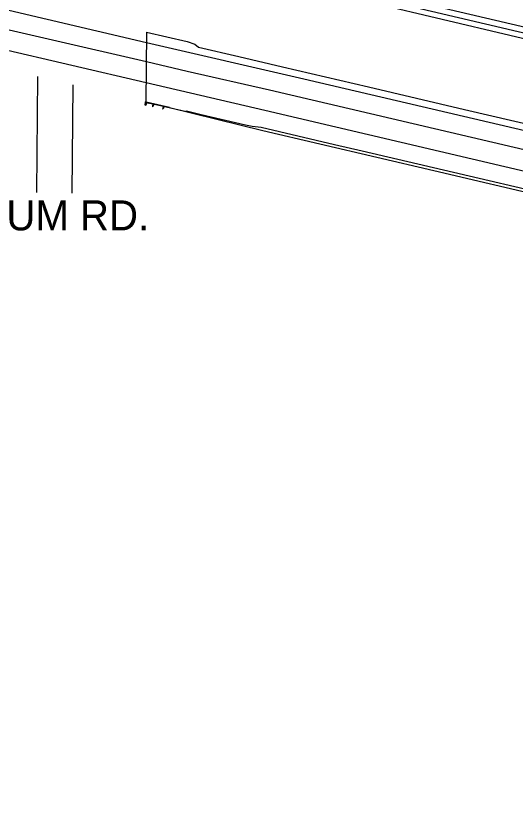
# Model space of a CAD drawing. Extents: x 1855721 to 1876784, y 662259 to 674089.
# Drawn here: x 1866935 to 1867234.5, y 670246.6 to 670728.1 of the extents above; entities that cross this region are included whole.
import ezdxf

# ---------------------------------------------------------------- set-up
doc = ezdxf.new("R2010")
doc.units = 0
for name, color, linetype in [('_CIVIL_CONSTRUCTION', 7, 'Continuous'), ('GE_X_Alignment_100_Bearings', 7, 'Continuous'), ('GE_X_Alignment_100_Curve_Data', 7, 'Continuous'), ('PV_X_EOP', 7, 'Continuous'), ('RD_P_GR_Rt', 7, 'Continuous'), ('SC_Scratch1', 7, 'Continuous'), ('ST_Details', 7, 'Continuous'), ('ST_Text', 7, 'Continuous')]:
    doc.layers.add(name, color=color, linetype=linetype)

msp = doc.modelspace()

# ---------------------------------------------------------------- linework, layer by layer
at = {"layer": '_CIVIL_CONSTRUCTION'}
msp.add_line((1867013.16, 670718.5), (1867012.76, 670676.58), dxfattribs=at)
msp.add_lwpolyline([(1867012.87, 670688.3), (1867083.99, 670671.71), (1867437.1, 670588.95), (1867669.88, 670534.52), (1867845.14, 670493.53), (1867928.1, 670474.12), (1868136.01, 670425.34)], dxfattribs=at)
at = {"layer": 'GE_X_Alignment_100_Bearings'}
msp.add_lwpolyline([(1866897.79, 670727.56), (1867013.17, 670700.87), (1867037.56, 670695.16), (1867086.73, 670683.9), (1867440.47, 670601.13), (1867916.5, 670489.44), (1868183.18, 670427.04), (1868411.44, 670373.26), (1868504.91, 670351.9), (1868605.05, 670329.69), (1868693.65, 670312.21), (1868779.08, 670297.26), (1868870.16, 670283.95), (1868961.03, 670272.66), (1869050.13, 670263.7), (1869134.71, 670256.54), (1869222.33, 670251.7), (1869304.01, 670248.74), (1869402.4, 670246.63)], dxfattribs=at)
at = {"layer": 'GE_X_Alignment_100_Curve_Data'}
for p, q in [((1866897.79, 670739.26), (1867013.1, 670712.33)), ((1866897.69, 670715.1), (1867012.95, 670688.28))]:
    msp.add_line(p, q, dxfattribs=at)
for points in [[(1869211.64, 670324.7), (1869181.41, 670325.88), (1869077.51, 670333.11), (1869033.93, 670337.15), (1868967.25, 670343.85), (1868933.99, 670347.93), (1868871.59, 670355.8), (1868843.23, 670360.06), (1868778.87, 670370.61), (1868737.1, 670377.6), (1868640.12, 670396.37), (1868613, 670401.82), (1868516.09, 670423.09), (1868416.31, 670446.1), (1868369.24, 670457), (1868181.82, 670500.43), (1868125.22, 670513.56), (1867987.22, 670546.13), (1867875.52, 670572.37), (1867459.74, 670669.94), (1867105.25, 670753), (1867057.66, 670764.25), (1867013.85, 670774.61)], [(1867013.1, 670712.33), (1867107.39, 670690.63), (1867437.01, 670613.48), (1867511.99, 670595.88), (1867874.8, 670510.7), (1867950.06, 670493.07), (1868168.73, 670441.99)]]:
    msp.add_lwpolyline(points, dxfattribs=at)
at = {"layer": 'PV_X_EOP'}
for p, q in [((1866947.78, 670691.88), (1866947.22, 670622.51)), ((1866969.01, 670686.85), (1866968.49, 670622.05))]:
    msp.add_line(p, q, dxfattribs=at)
at = {"layer": 'RD_P_GR_Rt'}
for points in [[(1867034.44, 670763.29), (1867109.18, 670745.61), (1867271.29, 670707.11), (1867411.77, 670673.57)], [(1867026.89, 670673.38), (1867082.92, 670659.65), (1867185.32, 670635.62), (1867324.6, 670602.93), (1867471.47, 670568.33), (1867621.14, 670533.37), (1867799.25, 670491.42), (1867900.04, 670468.06)]]:
    msp.add_lwpolyline(points, dxfattribs=at)
at = {"layer": 'SC_Scratch1'}
for points in [[(1867013.89, 670768.45), (1867037.96, 670762.82), (1867045.83, 670762.4), (1867047.65, 670762.28), (1867086.65, 670753.54), (1867086.77, 670753.98), (1867365.21, 670688.46), (1867472.77, 670663.16), (1867790.05, 670588.69), (1867994.77, 670540.69), (1868234.96, 670484.68)], [(1867013.16, 670718.5), (1867037.51, 670712.94), (1867042, 670711.21), (1867044.2, 670709.59), (1867068.36, 670703.88), (1867094.66, 670697.68), (1867146.22, 670685.66), (1867203.66, 670672.26), (1867275.17, 670655.59), (1867370.07, 670633.46), (1867484.93, 670606.62), (1867622.01, 670574.46), (1867714.16, 670552.85), (1867800.86, 670532.51), (1867916.15, 670505.47), (1867988.09, 670488.56), (1868059.57, 670471.76), (1868156.47, 670448.98)], [(1867012.76, 670676.58), (1867037.02, 670670.91), (1867037, 670671.33), (1867045.87, 670669.27), (1867072.52, 670663.05), (1867076.49, 670662.12), (1867081.85, 670661.49), (1867125.8, 670651.23), (1867142.34, 670647.38), (1867309.92, 670608.36), (1867388.87, 670589.99), (1867589.78, 670542.95), (1867666.82, 670524.88), (1867762.75, 670502.38), (1867895.63, 670471.22), (1867930.89, 670462.97), (1868063.82, 670432.01), (1868131.69, 670416.2), (1868263.49, 670385.32)]]:
    msp.add_lwpolyline(points, dxfattribs=at)
at = {"layer": 'ST_Details'}
for p, q in [((1867012.4, 670676.37), (1867012.1, 670675.02)), ((1867016.07, 670675.54), (1867012.17, 670676.42)), ((1867012.47, 670676.35), (1867012.17, 670675)), ((1867012.29, 670676.49), (1867012.27, 670676.4)), ((1867026.82, 670673.11), (1867012.27, 670676.4)), ((1867012.61, 670676.41), (1867012.29, 670676.49)), ((1867012.38, 670676.54), (1867012.37, 670676.47)), ((1867012.57, 670676.5), (1867012.38, 670676.54)), ((1867012.43, 670676.59), (1867012.41, 670676.53)), ((1867012.72, 670676.3), (1867012.42, 670674.95)), ((1867012.53, 670676.59), (1867012.45, 670676.61)), ((1867012.46, 670676.58), (1867012.45, 670676.53)), ((1867012.51, 670676.57), (1867012.5, 670676.51)), ((1867012.55, 670676.56), (1867012.53, 670676.51)), ((1867012.57, 670676.5), (1867012.55, 670676.43)), ((1867012.86, 670676.5), (1867012.61, 670676.41)), ((1867013.54, 670676.4), (1867013.48, 670676.13)), ((1867013.78, 670676.06), (1867013.84, 670676.33)), ((1867011.99, 670674.96), (1867012.01, 670675.04)), ((1867012.88, 670674.75), (1867011.99, 670674.96)), ((1867012.9, 670674.84), (1867012.01, 670675.04)), ((1867012.8, 670676.28), (1867012.49, 670674.93)), ((1867013.05, 670676.22), (1867012.75, 670674.87)), ((1867013.12, 670676.21), (1867012.82, 670674.86)), ((1867012.88, 670674.75), (1867012.9, 670674.84)), ((1867013.12, 670676.21), (1867013.06, 670676.22)), ((1867013.69, 670676.24), (1867013.68, 670676.21)), ((1867013.7, 670676.19), (1867013.92, 670676.14)), ((1867013.93, 670676.21), (1867013.71, 670676.26)), ((1867013.94, 670676.15), (1867013.95, 670676.18)), ((1867014.37, 670676.08), (1867014.37, 670676.06)), ((1867014.6, 670675.98), (1867014.38, 670676.03)), ((1867014.62, 670676.05), (1867014.4, 670676.1)), ((1867014.47, 670675.9), (1867014.53, 670676.18)), ((1867014.63, 670676), (1867014.64, 670676.02)), ((1867014.78, 670676.12), (1867014.71, 670675.85)), ((1867016.69, 670673.88), (1867016.69, 670673.9)), ((1867016.84, 670673.87), (1867016.69, 670673.9)), ((1867017.01, 670673.81), (1867016.69, 670673.88)), ((1867016.95, 670675.33), (1867016.73, 670674.36)), ((1867016.77, 670674.34), (1867016.73, 670674.35)), ((1867016.78, 670674.37), (1867016.77, 670674.34)), ((1867017.13, 670674.29), (1867016.78, 670674.37)), ((1867017.11, 670674.29), (1867016.79, 670674.36)), ((1867016.79, 670674.35), (1867016.79, 670674.36)), ((1867016.94, 670674.31), (1867016.79, 670674.35)), ((1867016.84, 670673.87), (1867016.94, 670674.31)), ((1867016.86, 670673.86), (1867016.96, 670674.31)), ((1867017.01, 670673.83), (1867016.86, 670673.86)), ((1867017.26, 670675.66), (1867016.93, 670674.21)), ((1867017.39, 670675.24), (1867016.96, 670675.34)), ((1867017.11, 670674.27), (1867016.96, 670674.31)), ((1867016.97, 670674.3), (1867016.97, 670674.29)), ((1867017.12, 670674.26), (1867016.97, 670674.29)), ((1867016.99, 670674.19), (1867017.02, 670674.31)), ((1867017, 670674.28), (1867016.99, 670674.23)), ((1867017.07, 670674.2), (1867016.99, 670674.22)), ((1867017.05, 670674.18), (1867016.99, 670674.19)), ((1867017.01, 670673.81), (1867017.01, 670673.83)), ((1867017.24, 670675.28), (1867017.02, 670674.31)), ((1867017.05, 670674.18), (1867017.08, 670674.3)), ((1867017.3, 670675.26), (1867017.08, 670674.3)), ((1867017.09, 670674.26), (1867017.08, 670674.21)), ((1867017.11, 670674.27), (1867017.11, 670674.29)), ((1867017.13, 670674.29), (1867017.12, 670674.26)), ((1867017.12, 670674.27), (1867017.12, 670674.25)), ((1867017.16, 670674.26), (1867017.12, 670674.26)), ((1867017.39, 670675.23), (1867017.17, 670674.26)), ((1867022.78, 670672.5), (1867022.78, 670672.52)), ((1867022.94, 670672.49), (1867022.78, 670672.52)), ((1867023.1, 670672.43), (1867022.78, 670672.5)), ((1867023.04, 670673.95), (1867022.82, 670672.98)), ((1867022.87, 670672.96), (1867022.83, 670672.97)), ((1867022.87, 670672.99), (1867022.87, 670672.96)), ((1867023.23, 670672.91), (1867022.87, 670672.99)), ((1867023.21, 670672.91), (1867022.89, 670672.98)), ((1867022.89, 670672.97), (1867022.89, 670672.98)), ((1867023.04, 670672.93), (1867022.89, 670672.97)), ((1867022.94, 670672.49), (1867023.04, 670672.93)), ((1867022.95, 670672.48), (1867023.05, 670672.93)), ((1867023.11, 670672.45), (1867022.95, 670672.48)), ((1867023.35, 670674.28), (1867023.02, 670672.83)), ((1867023.48, 670673.86), (1867023.05, 670673.96)), ((1867023.21, 670672.89), (1867023.05, 670672.93)), ((1867023.07, 670672.92), (1867023.06, 670672.91)), ((1867023.22, 670672.88), (1867023.06, 670672.91)), ((1867023.09, 670672.9), (1867023.08, 670672.86)), ((1867023.09, 670672.81), (1867023.12, 670672.93)), ((1867023.16, 670672.82), (1867023.09, 670672.84)), ((1867023.15, 670672.8), (1867023.09, 670672.81)), ((1867023.1, 670672.43), (1867023.11, 670672.45)), ((1867023.33, 670673.9), (1867023.12, 670672.93)), ((1867023.15, 670672.8), (1867023.18, 670672.92)), ((1867023.39, 670673.88), (1867023.18, 670672.92)), ((1867023.19, 670672.88), (1867023.18, 670672.83)), ((1867023.21, 670672.89), (1867023.21, 670672.91)), ((1867023.23, 670672.91), (1867023.22, 670672.88)), ((1867023.22, 670672.89), (1867023.22, 670672.88)), ((1867023.26, 670672.88), (1867023.22, 670672.88)), ((1867023.49, 670673.85), (1867023.27, 670672.88)), ((1867025.81, 670673.34), (1867025.87, 670673.61)), ((1867025.97, 670673.3), (1867026.03, 670673.58)), ((1867026.66, 670673.14), (1867026.72, 670673.42)), ((1867026.82, 670673.11), (1867026.89, 670673.38))]:
    msp.add_line(p, q, dxfattribs=at)
for points in [[(1867012.15, 670674.92), (1867012.14, 670674.89), (1867012.07, 670674.9), (1867012.08, 670674.93)], [(1867012.09, 670674.9), (1867012.09, 670674.87), (1867012.11, 670674.87), (1867012.12, 670674.89)], [(1867012.47, 670674.85), (1867012.46, 670674.82), (1867012.39, 670674.83), (1867012.4, 670674.86)], [(1867012.42, 670674.83), (1867012.41, 670674.8), (1867012.43, 670674.79), (1867012.44, 670674.82)], [(1867012.8, 670674.77), (1867012.79, 670674.74), (1867012.72, 670674.76), (1867012.73, 670674.79)], [(1867012.74, 670674.75), (1867012.74, 670674.72), (1867012.76, 670674.72), (1867012.77, 670674.75)]]:
    msp.add_lwpolyline(points, dxfattribs=at)
for centre, start, end in [((1867016.74, 670674.36), 167.2516, 257.2516), ((1867016.96, 670675.33), 77.2516, 167.2516), ((1867017.16, 670674.26), 257.2516, 347.2516), ((1867017.38, 670675.23), 347.2516, 77.2516), ((1867022.83, 670672.98), 167.2516, 257.2516), ((1867023.05, 670673.95), 77.2516, 167.2516), ((1867023.26, 670672.89), 257.2516, 347.2516), ((1867023.48, 670673.85), 347.2516, 77.2516)]:
    msp.add_arc(centre, 0.01, start, end, dxfattribs=at)
for centre, major_axis, ratio, start_param, end_param in [((1867012.44, 670676.59), (-0.0047, -0.0208), 0.806404, 1.488236, 4.755612), ((1867012.48, 670676.56), (0.0076, 0.0338), 0.806404, 5.077454, 7.489005), ((1867012.53, 670676.57), (-0.0047, -0.0208), 0.806404, 1.488236, 4.755612), ((1867012.96, 670676.24), (0.072, 0.276), 0.944544, 0.080888, 0.65782), ((1867013.7, 670676.21), (-0.005, -0.0222), 0.944544, 4.712389, 6.283185), ((1867013.71, 670676.23), (0.005, 0.0222), 0.944544, 0, 1.570796), ((1867013.92, 670676.16), (-0.005, -0.0222), 0.944544, 0, 1.570796), ((1867013.93, 670676.18), (-0.005, -0.0222), 0.944544, 1.570796, 3.141593), ((1867014.39, 670676.05), (-0.005, -0.0222), 0.944544, 4.712389, 6.283185), ((1867014.39, 670676.08), (0.005, 0.0222), 0.944544, 0, 1.570796), ((1867014.61, 670676), (-0.005, -0.0222), 0.944544, 0, 1.570796), ((1867014.61, 670676.03), (-0.005, -0.0222), 0.944544, 1.570796, 3.141593), ((1867017, 670674.23), (0.0031, 0.0136), 0.929688, 1.586202, 2.897406), ((1867017.07, 670674.22), (0.0031, 0.0136), 0.929688, 3.345604, 4.722982), ((1867017.27, 670675.27), (-0.0914, 0.0207), 0.312583, 3.061844, 6.362934), ((1867023.09, 670672.85), (0.0031, 0.0136), 0.929688, 1.586202, 2.897406), ((1867023.17, 670672.84), (0.0031, 0.0136), 0.929688, 3.345604, 4.722982), ((1867023.37, 670673.89), (-0.0914, 0.0207), 0.312583, 3.061844, 6.362934)]:
    msp.add_ellipse(centre, major_axis=major_axis, ratio=ratio, start_param=start_param, end_param=end_param, dxfattribs=at)
for centre, major_axis, ratio in [((1867013.81, 670676.2), (-0.0159, -0.0454), 0.977529), ((1867014.5, 670676.04), (-0.0159, -0.0454), 0.977529), ((1867026, 670673.44), (-0.0488, 0.011), 0.75), ((1867026.69, 670673.28), (-0.0488, 0.011), 0.75)]:
    msp.add_ellipse(centre, major_axis=major_axis, ratio=ratio, dxfattribs=at)
at = {"layer": 'ST_Text'}
msp.add_line((1867026.89, 670673.38), (1867013.01, 670676.52), dxfattribs=at)

# ---------------------------------------------------------------- texts
at = {"layer": 'SC_Scratch1'}
msp.add_text('GYPSUM RD.', height=18, dxfattribs=at).set_placement((1866862.29, 670599.76))

doc.saveas('drawing.dxf')
